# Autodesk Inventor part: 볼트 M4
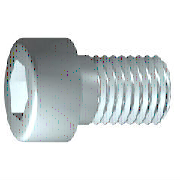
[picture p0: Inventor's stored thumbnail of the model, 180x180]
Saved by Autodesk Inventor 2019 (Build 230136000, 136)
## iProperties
IsCustomPart: 1
Created: 2012-02
Part Number: 볼트 M4
Material: 강철, 연강
Description: 6각머리 태핑 나사
Document SubType Name: Modeling
Standard: KS B 1003
Designer: test
Standards Organization: KS
Language: ko-KR
Size Designation: M 4 x 10
Categories: <MemberInstance><Categories><Category DisplayName="조임쇠" InternalName="e4da775c-781d-43d5-af7c-5136215cf5a6" Mnemonic="FSTN"><Category DisplayName="볼트" InternalN
Density: 1 g/cm^3
Appearance: 강철
Author: test
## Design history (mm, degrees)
sketch "스케치1"
  geometry: L1 (-1, 0)-(10, 0); L2 (10, 0)-(10, 2); L3 (10, 2)-(1.75, 2); L4 (1.75, 2)-(1.32, 2); L5 (1.32, 2)-(0, 2); L6 (0, 2)-(0, 3.5); L7 (0, 3.5)-(-4, 3.5); L8 (-4, 3.5)-(-4, 1.732); L9 (-4, 1.732)-(-2, 1.732); L10 (-2, 1.732)-(-1, 0); L11 (-6.8, 0)-(12.8, 0) reference; L12 (0, -0.7)-(0, 4.2) reference; L13 (1.75, 2)-(0, 2)
  constraints: 22 end point, 6 parallel, 2 collinear, 2 perpendicular, 1 horizontal, 1 point on line
  dimensions: "d1" = 8.25 distance from line of L3.end L2 (= GEL); "d2" = 0.42952 distance of L4.end L3.end (computed from GAL); "d3" = 4 distance between parallel lines of L8 L6 (= KOH); "d4" = 2 distance of L8.end L9.end (= INTI); "d5" = 60 deg angle of L10 L1; "d6" = 4 diameter of L3 L1 (= GD); "d7" = 4 diameter of L5 L1 (= BDM); "d8" = 3.4641 diameter of L9 L1 (= 1.1547 x SW); "d9" = 7 diameter of L7 L1 (= KOD); "d26" = 10 distance between parallel lines of L12 L2 (= NLG)
revolve "본체" sketch "스케치1" stored, may be unused: angle "d10" = 90 deg
sketch "스케치2"
  geometry: L1 (0, -4.9)-(0, 4.9) reference; L2 (-4.9, 0)-(4.9, 0) reference; L3 (1.732, 0)-(0.866, -1.5); L4 (0.866, -1.5)-(-0.866, -1.5); L5 (-0.866, -1.5)-(-1.732, 0); L6 (-1.732, 0)-(-0.866, 1.5); L7 (-0.866, 1.5)-(0.866, 1.5); L8 (0.866, 1.5)-(1.732, 0); 2 further points
  constraints: 12 end point, 1 coincident, 1 horizontal alignment, 1 point on line, 12 other
extrude "슬롯" join sketch "스케치2" stored distance "d11" = 10; taper "d12" = 0 deg
workplane "Work Plane1"
fillet "Fillet2" dims "d30" = 0.1 (= R)
body "Solid1"
fillet "모깎기1" dims "d17" = 0.4 (= RR)
feature "스레드" dims "d13" = 8.25 (= GEL), "d14" = 0
chamfer "모따기1" distance "d15" = 0.42941 (= -0.5 x SPD + 0.5 x GD); stored, may be unused: second distance "d16" = 0.42941 (= GUL), angle "d27" = 45 deg
other parameters: "GD" = 4 (= NND) [user parameter; used in 2 equation terms], "NLG" = 10 [user parameter; used in 1 equation term], "GEL" = 8.25 [user parameter; used in 2 equation terms], "KOD" = 7 [user parameter; used in 1 equation term], "KOH" = 4 [user parameter; used in 1 equation term], "INTI" = 2 [user parameter; used in 1 equation term], "GAL" = 0.42941 (= 0.61345 x PTC) [user parameter; used in 1 equation term], "GUL" = 0.42941 (= 0.61345 x PTC) [user parameter; used in 1 equation term], "BDM" = 4 (= NND) [user parameter; used in 1 equation term], "SW" = 3 [user parameter; used in 2 equation terms], "RR" = 0.4 [user parameter; used in 1 equation term], "SPD" = 3.14117 (= NND - 1.2269 x PTC) [user parameter; used in 1 equation term], "d19" = 0, "d28" = 0, "d29" = 0, "R" = 0.1 [user parameter; used in 1 equation term], "PHH" = 0.2 [user parameter], "GD1" = 3.14117 (= THREADDIA - 1.2269 x PTC) [user parameter], "THREADDIA" = 4 [user parameter; used in 1 equation term], "FAWI" = 45 deg [user parameter], "TPU" = 14.28571 (computed from PTC) [user parameter], "PTC" = 0.7 [user parameter; used in 5 equation terms], "NND" = 4 [user parameter; used in 3 equation terms], "TOA" = 30 deg [user parameter], "E0" = 3.465 (= 1.155 x SW) [user parameter]
